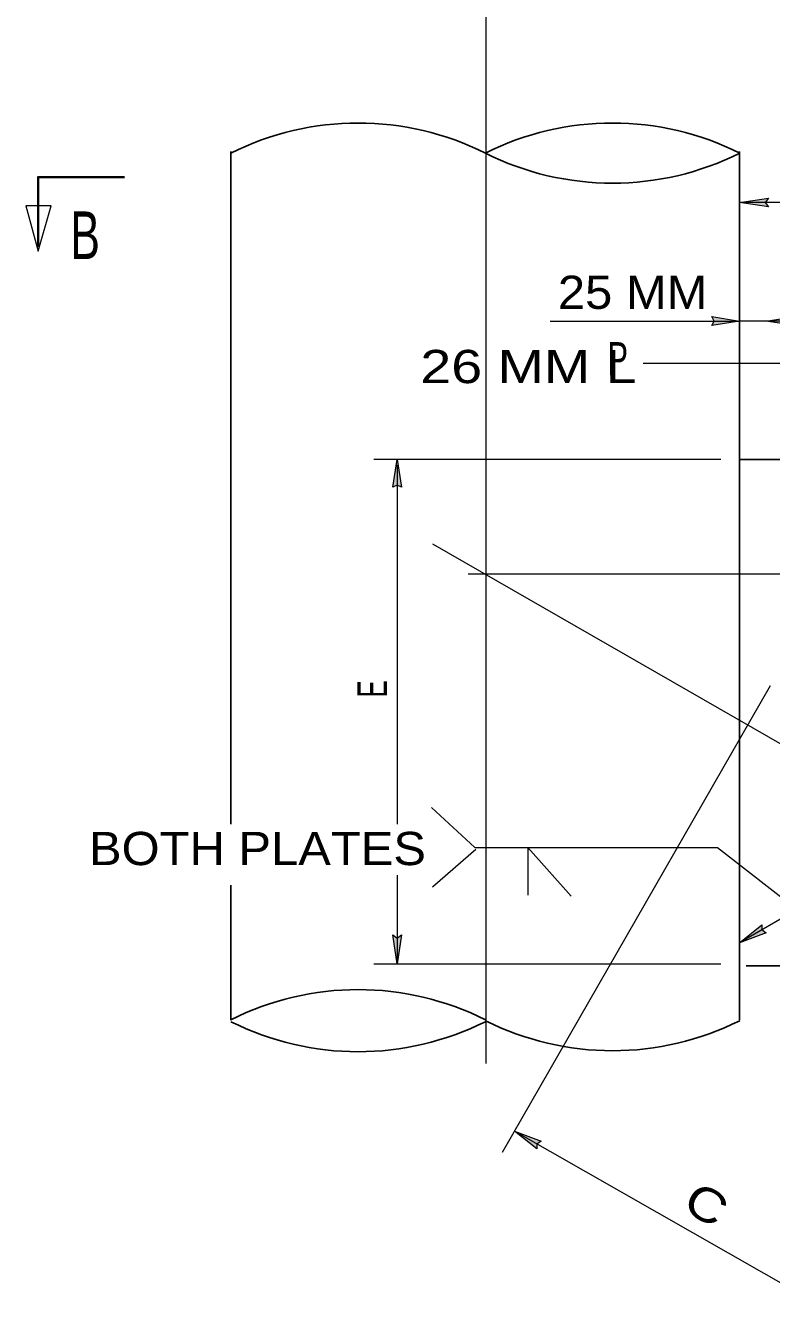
# Model space of a CAD drawing. Extents: x 312601.858 to 312602.699, y 144420.109 to 144420.704.
# Drawn here: x 312602.1038 to 312602.1711, y 144420.5252 to 144420.6417 of the extents above; entities that cross this region are included whole.
import ezdxf
from ezdxf.enums import TextEntityAlignment as Align

# ---------------------------------------------------------------- set-up
doc = ezdxf.new("R2010")
doc.units = 0
doc.header["$LTSCALE"] = 0.0012
doc.linetypes.add('DOT_DASHED', pattern=[7.7, 5, -1.2, 0.3, -1.2])
for name, color, linetype, lineweight in [('1', 7, 'Continuous', 25), ('2', 7, 'Continuous', 13), ('39', 7, 'Continuous', 13), ('9', 7, 'Continuous', 13)]:
    doc.layers.add(name, color=color, linetype=linetype, lineweight=lineweight)

msp = doc.modelspace()

# ---------------------------------------------------------------- hatches: boundary and pattern name
at = {"layer": '39'}
for points in [[(312602.1705, 144420.6258), (312602.1708, 144420.6254), (312602.1682, 144420.6258), (312602.1708, 144420.6262)], [(312602.1705, 144420.6258), (312602.1708, 144420.6254), (312602.1682, 144420.6258), (312602.1708, 144420.6262)], [(312602.1659, 144420.6151), (312602.1657, 144420.6155), (312602.1682, 144420.6151), (312602.1657, 144420.6147)], [(312602.1659, 144420.6151), (312602.1657, 144420.6155), (312602.1682, 144420.6151), (312602.1657, 144420.6147)], [(312602.1729, 144420.6151), (312602.1732, 144420.6147), (312602.1706, 144420.6151), (312602.1732, 144420.6155)], [(312602.1373, 144420.6003), (312602.1369, 144420.6001), (312602.1373, 144420.6026), (312602.1377, 144420.6001)], [(312602.1702, 144420.5602), (312602.1706, 144420.5599), (312602.1682, 144420.559), (312602.1702, 144420.5606)], [(312602.1373, 144420.5594), (312602.1377, 144420.5597), (312602.1373, 144420.5571), (312602.1369, 144420.5597)], [(312602.1373, 144420.5594), (312602.1377, 144420.5597), (312602.1373, 144420.5571), (312602.1369, 144420.5597)], [(312602.1499, 144420.5408), (312602.1499, 144420.5404), (312602.1479, 144420.542), (312602.1503, 144420.5411)]]:
    msp.add_hatch(color=256, dxfattribs=at).paths.add_polyline_path(points)

# ---------------------------------------------------------------- linework, layer by layer
at = {"layer": '1', "lineweight": 13}
for p, q in [((312602.1453, 144420.6488), (312602.1453, 144420.6372)), ((312602.1944, 144420.6258), (312602.1683, 144420.6258)), ((312602.1511, 144420.6151), (312602.1682, 144420.6151)), ((312602.1665, 144420.6026), (312602.1352, 144420.6026)), ((312602.1373, 144420.6021), (312602.1373, 144420.5697)), ((312602.1468, 144420.5401), (312602.171, 144420.5822)), ((312602.1443, 144420.5676), (312602.1404, 144420.5712)), ((312602.1444, 144420.5674), (312602.1405, 144420.564)), ((312602.1443, 144420.5676), (312602.1662, 144420.5676)), ((312602.1491, 144420.5676), (312602.1491, 144420.5633)), ((312602.1491, 144420.5676), (312602.153, 144420.5632)), ((312602.1373, 144420.5651), (312602.1373, 144420.5571)), ((312602.1352, 144420.5571), (312602.1665, 144420.5571)), ((312602.1773, 144420.5252), (312602.1479, 144420.542))]:
    msp.add_line(p, q, dxfattribs=at)
at = {"layer": '1', "linetype": 'DOT_DASHED', "lineweight": 13}
for p, q in [((312602.1453, 144420.6373), (312602.1453, 144420.5481)), ((312602.1405, 144420.595), (312602.1982, 144420.5618)), ((312602.1437, 144420.5923), (312602.2241, 144420.5923))]:
    msp.add_line(p, q, dxfattribs=at)
at = {"layer": '1'}
for p, q in [((312602.1223, 144420.5697), (312602.1223, 144420.6304)), ((312602.1682, 144420.552), (312602.1682, 144420.6304)), ((312602.1948, 144420.6026), (312602.1682, 144420.6026)), ((312602.1223, 144420.552), (312602.1223, 144420.5642)), ((312602.1688, 144420.5569), (312602.1829, 144420.5569))]:
    msp.add_line(p, q, dxfattribs=at)
at = {"layer": '1', "lineweight": 35}
msp.add_lwpolyline([(312602.1049, 144420.6218), (312602.1049, 144420.6281), (312602.1127, 144420.6281)], dxfattribs=at)
at = {"layer": '1', "lineweight": 13}
for points in [[(312602.1775, 144420.6151), (312602.1706, 144420.6151), (312602.1682, 144420.6151)], [(312602.1595, 144420.6113), (312602.1746, 144420.6113), (312602.1809, 144420.6026)]]:
    msp.add_lwpolyline(points, dxfattribs=at)
at = {"layer": '2'}
msp.add_lwpolyline([(312602.1662, 144420.5676), (312602.1734, 144420.562), (312602.1682, 144420.559)], dxfattribs=at)
at = {"layer": '2', "lineweight": 25}
for centre, start, end in [((312602.133785, 144420.607361), 63.38393, 116.61607), ((312602.156735, 144420.607361), 63.38393, 116.61607), ((312602.156735, 144420.653159), 243.38393, 296.61607), ((312602.133785, 144420.529151), 63.38393, 116.61607), ((312602.156735, 144420.574859), 243.38393, 296.61607), ((312602.133785, 144420.574769), 243.38393, 296.61607)]:
    msp.add_arc(centre, 0.025613, start, end, dxfattribs=at)
at = {"layer": '39'}
for points in [[(312602.1705, 144420.6258), (312602.1708, 144420.6254), (312602.1682, 144420.6258), (312602.1708, 144420.6262)], [(312602.1705, 144420.6258), (312602.1708, 144420.6254), (312602.1682, 144420.6258), (312602.1708, 144420.6262)], [(312602.1659, 144420.6151), (312602.1657, 144420.6155), (312602.1682, 144420.6151), (312602.1657, 144420.6147)], [(312602.1659, 144420.6151), (312602.1657, 144420.6155), (312602.1682, 144420.6151), (312602.1657, 144420.6147)], [(312602.1729, 144420.6151), (312602.1732, 144420.6147), (312602.1706, 144420.6151), (312602.1732, 144420.6155)], [(312602.1373, 144420.6003), (312602.1369, 144420.6001), (312602.1373, 144420.6026), (312602.1377, 144420.6001)], [(312602.1702, 144420.5602), (312602.1706, 144420.5599), (312602.1682, 144420.559), (312602.1702, 144420.5606)], [(312602.1373, 144420.5594), (312602.1377, 144420.5597), (312602.1373, 144420.5571), (312602.1369, 144420.5597)], [(312602.1373, 144420.5594), (312602.1377, 144420.5597), (312602.1373, 144420.5571), (312602.1369, 144420.5597)], [(312602.1499, 144420.5408), (312602.1499, 144420.5404), (312602.1479, 144420.542), (312602.1503, 144420.5411)]]:
    msp.add_lwpolyline(points, close=True, dxfattribs=at)
at = {"layer": '9'}
msp.add_lwpolyline([(312602.1038, 144420.6255), (312602.1049, 144420.6214), (312602.1061, 144420.6255)], close=True, dxfattribs=at)

# ---------------------------------------------------------------- texts
at = {"layer": '2'}
for s, height, width, p in [('B', 0.0043, 0.7, (312602.10915, 144420.6207)), ('25 MM', 0.003, 1.1, (312602.15855, 144420.6162)), ('26 MM L', 0.003, 1.25, (312602.14915, 144420.6095)), ('P', 0.003, 0.7, (312602.1572, 144420.6102)), ('BOTH PLATES', 0.003, 1.1, (312602.1247, 144420.566))]:
    msp.add_text(s, height=height, dxfattribs=dict(at, width=width)).set_placement(p, align=Align.CENTER)
for s, height, rotation, width, p in [('E', 0.0027, 90, 0.65, (312602.1364, 144420.5819)), ('C', 0.003, 329.036, 1.25, (312602.164428, 144420.534083))]:
    msp.add_text(s, height=height, rotation=rotation, dxfattribs=dict(at, width=width)).set_placement(p, align=Align.CENTER)

doc.saveas('drawing.dxf')
